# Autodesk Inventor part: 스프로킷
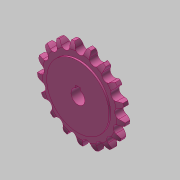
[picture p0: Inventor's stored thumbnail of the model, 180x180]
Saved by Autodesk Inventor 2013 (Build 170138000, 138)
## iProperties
Created: 2019-06
Part Number: 스프로킷
Material: 알루미늄 6061
Document SubType Name: Modeling
Designer: mduedu
Density: 1 g/cm^3
Author: mduedu
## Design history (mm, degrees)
sketch "스케치1"
  geometry: L1 (0, 0)-(-3.6, 0); L2 (-3.6, 0)-(-3.6, 32.203); L3 (-2, 38)-(0, 38); L4 (0, 38)-(0, 0); L5 (0, 0)-(3.6, 0); L6 (3.6, 0)-(3.6, 32.203); L7 (2, 38)-(0, 38); A1 r 13.5 centre (9.887, 31.6) between (-2, 38) and (-3.6, 32.203); A2 r 13.5 centre (-9.887, 31.6) between (3.6, 32.203) and (2, 38)
  constraints: 14 end point, 4 point on circle, 4 symmetric about line, 2 centre point, 2 perpendicular, 1 horizontal, 1 parallel, 1 other
  dimensions: "d0" = 76 diameter of L3 L1; "d2" = 7.2 distance between parallel lines of L6 L2; "d3" = 1.6 distance from line of L3.start L2; "d4" = 6.4 distance from line of A2.centre L3; "d5" = 13.5 radius of A1
revolve "회전1" sketch "스케치1" stored, may be unused: angle "d6" = 90 deg
sketch "스케치2"
  geometry: L1 (34.56, 0)-(-34.56, 0); A1 r 34.56 centre (0, 0) between (34.56, 0) and (30.537, -16.182); A2 r 3.975 centre (34.56, 0) between (33.601, 3.858) and (33.601, -3.858); A3 r 12.7 centre (30.537, -16.182) between (37.583, -5.616) and (33.601, -3.858); A4 r 12.7 centre (30.537, 16.182) between (33.601, 3.858) and (37.583, 5.616); A5 r 38 centre (0, 0) between (37.583, -5.616) and (37.583, 5.616); 2 further points
  constraints: 11 point on circle, 5 centre point, 2 coincident, 2 end point, 2 symmetric about line, 1 horizontal, 1 horizontal alignment, 1 tangent, 3 other
  dimensions: "d7" = 69.12 diameter of A1; "d8" = 7.95 diameter of A2; "d9" = 12.7 radius of A3
extrude "돌출1" cut sketch "스케치2" stored distance "d10" = 10; taper "d11" = 0 deg
sketch "스케치3"
  geometry: C1 r 27 at (0, 0); 1 further point
  constraints: 1 centre point, 1 coincident
  dimensions: "d15" = 54 diameter of C1
extrude "돌출2" join sketch "스케치3" stored distance "d16" = 10; taper "d17" = 0 deg
sketch "스케치4"
  geometry: C1 r 11 at (0, 0); 1 further point
  constraints: 1 centre point, 1 coincident
  dimensions: "d18" = 22 diameter of C1
extrude "돌출3" join sketch "스케치4" distance "d19" = 11; taper "d20" = 0 deg
fillet "모깎기1" dims "d21" = 3
sketch "스케치5"
  geometry: L1 (-2, 5.657)-(2, 5.657); L2 (2, 5.657)-(2, 7.8); L3 (2, 7.8)-(-2, 7.8); L4 (-2, 7.8)-(-2, 5.657); A1 r 6 centre (0, 0) between (-2, 5.657) and (2, 5.657); 1 further point
  constraints: 8 end point, 2 parallel, 2 point on circle, 1 centre point, 1 coincident, 1 horizontal, 1 perpendicular
  dimensions: "d24" = 13.8 dimension on A1 L3; "d26" = 4 distance between parallel lines of L2 L4; "d27" = 12 diameter of A1
extrude "돌출4" cut sketch "스케치5" stored distance "d28" = 11; taper "d29" = 0 deg
chamfer "모따기1" distance "d30" = 0.5; stored, may be unused: second distance "d31" = 2, angle "d32" = 45 deg
node "솔리드1"
pattern_circular "원형 패턴1" dims angle "d13" = 360 deg
